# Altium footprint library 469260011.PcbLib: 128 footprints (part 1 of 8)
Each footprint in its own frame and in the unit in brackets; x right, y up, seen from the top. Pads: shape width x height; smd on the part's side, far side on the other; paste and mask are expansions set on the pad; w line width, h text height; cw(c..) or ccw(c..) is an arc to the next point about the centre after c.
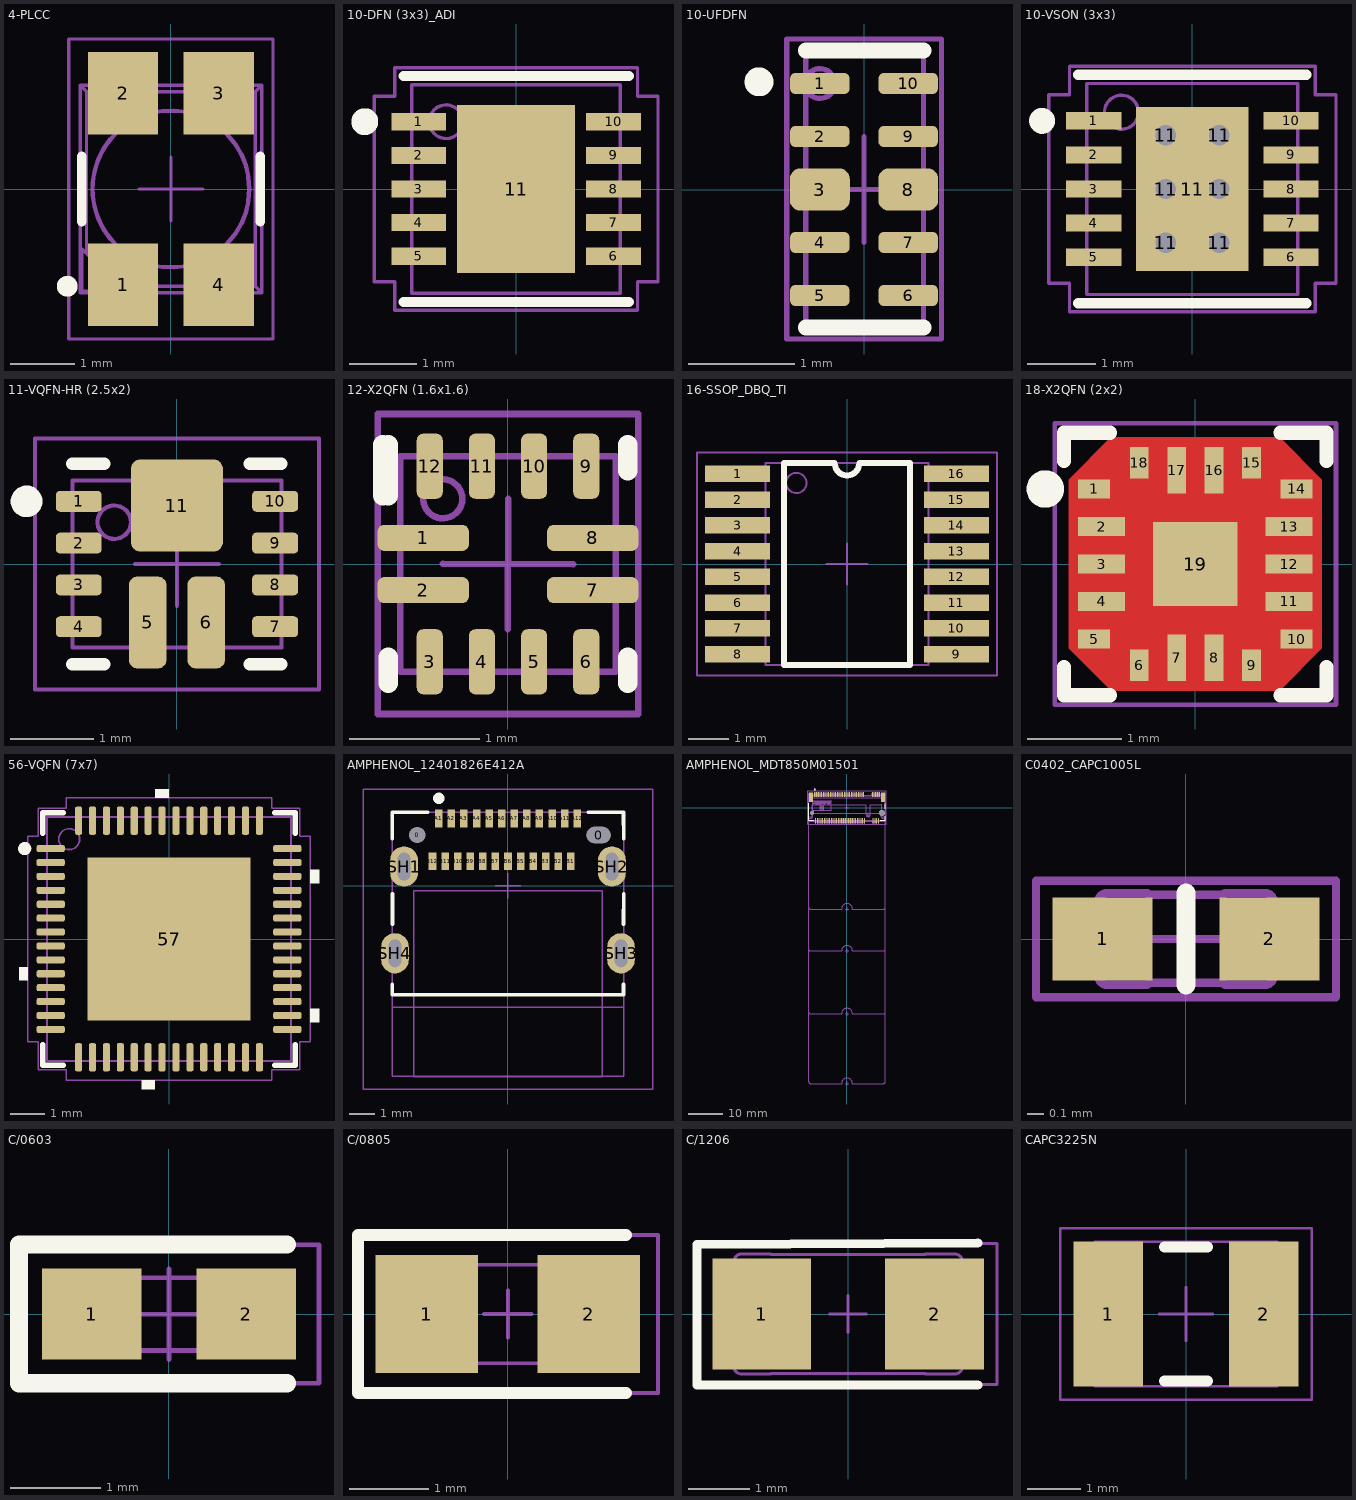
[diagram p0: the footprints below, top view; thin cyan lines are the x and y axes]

## 4-PLCC [mm] "LED RGB DIFFUSED 4PLCC SMD 3.2 x 2.8 x 1.9 mm"
height 1.9
pads (4):
  rect 1.1x1.3 smd: 1(-0.75,-1.5) 2(-0.75,1.5) 3(0.75,1.5) 4(0.75,-1.5)
Top Overlay:
  circle w0.254: c-1.626,-1.524 r0.036
  lines w0.152: -1.397,-0.508 -1.397,0.508 ; 1.397,-0.508 1.397,0.508
Top Assembly:
  circle w0.05: c0,0 r1.23
  circle w0.05: c0,0 r1.219
  circle w0.05: c0,0 r1.238
  lines w0.05: -1.421,-1.624 -1.396,-1.599 ; -1.421,-1.624 -1.421,1.624 ; -1.421,-1.624 1.421,-1.624 ; -1.421,1.624 -1.321,1.524 ; -1.421,1.624 1.421,1.624 ; -1.396,-1.599 -1.396,-0.938 -1.321,-1.012 ; -1.396,-1.599 -0.734,-1.599 -0.809,-1.524 ; -1.321,-1.012 -1.321,1.524 ; -1.321,-1.012 -0.809,-1.524 ; -1.321,1.524 1.321,1.524 ; -1.219,-1.676 -1.219,-1.778 -0.508,-1.778 -0.508,-1.676 ; -1.219,-1.676 -0.508,-1.676 ; -1.219,-1.676 -1.219,-1.626 -1.422,-1.626 -1.422,1.626 -1.219,1.626 -1.219,1.676 ; -1.219,1.676 -1.219,1.778 -0.508,1.778 -0.508,1.676 ; -1.219,1.676 -0.508,1.676 ; -0.809,-1.524 1.321,-1.524 ; -0.508,-1.676 -0.508,-1.626 0.508,-1.626 0.508,-1.676 ; -0.508,1.676 -0.508,1.626 0.508,1.626 0.508,1.676 ; 0.508,-1.676 1.219,-1.676 ; 0.508,-1.676 0.508,-1.778 1.219,-1.778 1.219,-1.676 ; 0.508,1.676 1.219,1.676 ; 0.508,1.676 0.508,1.778 1.219,1.778 1.219,1.676 ; 1.219,-1.676 1.219,-1.626 1.422,-1.626 1.422,1.626 1.219,1.626 1.219,1.676 ; 1.321,-1.524 1.421,-1.624 ; 1.321,-1.524 1.321,1.524 ; 1.321,1.524 1.421,1.624 ; 1.421,-1.624 1.421,1.624
  text ".Designator" at -2.251,-0.226 h1
Top Courtyard:
  lines w0.05: -0.498,0 0.502,0 ; 0,-0.5 0,0.5 ; -1.6,-2.35 -1.6,2.35 1.6,2.35 1.6,-2.35 -1.6,-2.35
3D body "User Library-ASMB-MTB0-0A3A2.step": height 1.9, standoff 0, extent -1.388,-1.75 1.412,1.75

## 10-DFN (3x3)_ADI [mil] "10-Lead Plastic DFN (3mm ? 3mm), 10-WFDFN Exposed Pad"
height 31.5
pads (11):
  rect 32x10 smd paste+0 mask+0: 1(-57,39.37) 2(-57,19.68) 3(-57,0) 4(-57,-19.68) 5(-57,-39.37) 6(57,-39.37) 7(57,-19.68) 8(57,0) 9(57,19.68) 10(57,39.37)
  rect 69x98 smd paste+0 mask+0: 11(0,0)
Top Overlay:
  circle w7.87: c-88.58,39.37 r3.94
  lines w5.91: -66,-66 66,-66 ; -66,66 66,66
Top Assembly:
  circle w1.97: c-41,39.37 r9.84
  lines w1.97: -61,-61 -61,61 61,61 61,-61 -61,-61
  text ".Designator" at -67.02,-8.15 h39.37
Top Courtyard:
  lines w1.97: -19.68,0 19.68,0 ; 0,-19.68 0,19.68 ; -83,-54.37 -71,-54.37 -71,-71 71,-71 71,-54.37 83,-54.37 83,54.37 71,54.37 71,71 -71,71 -71,54.37 -83,54.37 -83,-54.37
3D body "TDFN 10P.STEP": height 30.4, standoff 0.48, extent -59.45,-59.06 59.45,59.05

## 10-UFDFN [mm] "TVS Diode Surface Mount U-DFN2510-10 (2.5x1.0mm)"
height 0.605
pads (10):
  rrect50% 0.56x0.2 smd mask+0.07: 1(-0.417,1) 2(-0.417,0.5) 4(-0.417,-0.5) 5(-0.417,-1) 6(0.417,-1) 7(0.417,-0.5) 9(0.417,0.5) 10(0.417,1)
  rrect50% 0.565x0.4 smd paste-0.02 mask+0.07: 3(-0.417,0) 8(0.417,0)
Top Overlay:
  circle w0.15: c-0.991,1.016 r0.061
  lines w0.15: -0.55,-1.3 0.56,-1.3 ; -0.55,1.31 0.56,1.31
Top Assembly:
  circle w0.05: c-0.417,1 r0.14
  lines w0.05: -0.55,-1.3 0.56,-1.3 0.56,1.3 -0.55,1.3 -0.55,-1.3
  text ".Designator" at -2.252,-0.226 h1
Top Courtyard:
  lines w0.05: -0.5,0 0.5,0 ; 0,-0.5 0,0.5 ; -0.73,-1.41 0.73,-1.41 0.73,1.42 -0.73,1.42 -0.73,-1.41
3D body "PESD1LVDS,115.STEP": height 0.5, standoff 0, extent -0.5,-1.25 0.5,1.25

## 10-VSON (3x3) [mil] "10-VFDFN Exposed Pad, DRC (TI)"
height 39.37
pads (17):
  rect 32x10 smd paste+0 mask+0: 1(-57,39.37) 2(-57,19.68) 3(-57,0) 4(-57,-19.68) 5(-57,-39.37) 6(57,-39.37) 7(57,-19.68) 8(57,0) 9(57,19.68) 10(57,39.37)
  round 31.5 hole 11.81 paste+0 mask-20: 11(-15.5,-31) 11(-15.5,0) 11(-15.5,31) 11(15.5,-31) 11(15.5,0) 11(15.5,31)
  rect 65x95 smd paste-47 mask-47: 11(0,0)
Top Overlay:
  circle w7.87: c-86.84,39.37 r3.54
  lines w5.91: -66,-66 66,-66 ; -66,66 66,66
Top Paste:
  region: 6,-34.94 -6,-34.94 -11.56,-40.5 -11.56,-44.55 11.56,-44.55 11.56,-40.5
  region: -25,-34.94 -29.55,-34.94 -29.55,-44.55 -19.44,-44.55 -19.44,-40.5
  region: 29.55,-34.94 25,-34.94 19.44,-40.5 19.44,-44.55 29.55,-44.55
  region: -25,-3.94 -29.55,-3.94 -29.55,-27.06 -25,-27.06 -19.44,-21.5 -19.44,-9.5
  region: 29.55,-3.94 25,-3.94 19.44,-9.5 19.44,-21.5 25,-27.06 29.55,-27.06
  region: 6,-3.94 -6,-3.94 -11.56,-9.5 -11.56,-21.5 -6,-27.06 6,-27.06 11.56,-21.5 11.56,-9.5
  region: 6,27.06 -6,27.06 -11.56,21.5 -11.56,9.5 -6,3.94 6,3.94 11.56,9.5 11.56,21.5
  region: -25,27.06 -29.55,27.06 -29.55,3.94 -25,3.94 -19.44,9.5 -19.44,21.5
  region: 29.55,27.06 25,27.06 19.44,21.5 19.44,9.5 25,3.94 29.55,3.94
  region: 11.56,44.55 -11.56,44.55 -11.56,40.5 -6,34.94 6,34.94 11.56,40.5
  region: -19.44,44.55 -29.55,44.55 -29.55,34.94 -25,34.94 -19.44,40.5
  region: 29.55,44.55 19.44,44.55 19.44,40.5 25,34.94 29.55,34.94
Top Solder:
  region: -35,-50 -35,-38.87 35,-38.87 35,-50
  region: -35,-23.13 -35,-7.87 35,-7.87 35,-23.13
  region: -35,7.87 -35,23.13 35,23.13 35,7.87
  region: 23.37,-50 23.37,50 35,50 35,-50
  region: 7.63,-50 7.63,50 -7.63,50 -7.63,-50
  region: -35,-50 -35,50 -23.37,50 -23.37,-50
  region: -35,38.87 -35,50 35,50 35,38.87
Top Assembly:
  circle w1.97: c-41,44.37 r9.84
  lines w1.97: -61,-61 61,-61 61,61 -61,61 -61,-61
  text ".Designator" at -88.67,-8.9 h39.37
Top Courtyard:
  lines w1.97: -19.68,0 19.68,0 ; 0,-19.68 0,19.68 ; -83,-54.37 -71,-54.37 -71,-71 71,-71 71,-54.37 83,-54.37 83,54.37 71,54.37 71,71 -71,71 -71,54.37 -83,54.37 -83,-54.37
3D body "SN65HVD01DRCR.step": height 39.37, standoff 0, extent -59.06,-59.06 59.06,59.06

## 11-VQFN-HR (2.5x2) [mm] "2.0-mm x 2.5-mm VQFN HotRod Package (TI)"
height 1
pads (11):
  rrect40% 0.55x0.25 smd mask+0: 1(-1.175,0.75) 2(-1.175,0.25) 3(-1.175,-0.25) 4(-1.175,-0.75) 7(1.175,-0.75) 8(1.175,-0.25) 9(1.175,0.25) 10(1.175,0.75)
  rrect45% 0.45x1.1 smd paste-2 mask+0: 5(-0.35,-0.7) 6(0.35,-0.7)
  rrect19% 1.1x1.1 smd paste-2 mask+0: 11(0,0.7)
Top Overlay:
  circle w0.2: c-1.8,0.75 r0.09
  lines w0.15: -1.25,-1.2 -0.87,-1.2 ; -1.25,1.2 -0.87,1.2 ; 0.87,-1.2 1.25,-1.2 ; 0.87,1.2 1.25,1.2
Top Paste:
  drawing of 5 lines, arcs and shapes, not listed
Top Solder:
  drawing of 11 lines, arcs and shapes, not listed
Top Assembly:
  circle w0.05: c-0.75,0.5 r0.2
  lines w0.05: -1.25,-1 1.25,-1 1.25,1 -1.25,1 -1.25,-1
  text ".Designator" at -2.252,-0.226 h1
Top Courtyard:
  lines w0.05: -0.5,0 0.5,0 ; 0,-0.5 0,0.5 ; -1.7,-1.5 1.7,-1.5 1.7,1.5 -1.7,1.5 -1.7,-1.5
3D body "step_temp.STEP": height 1, standoff 0, extent -1.25,-1 1.25,1

## 12-X2QFN (1.6x1.6) [mm] "12-XFQFN 1.60 mm × 1.60 mm, RWB0012A (TI)"
height 0.4
pads (12):
  rrect50% 0.7x0.2 smd paste-0.337 mask+0.051: 1(-0.65,0.2) 2(-0.65,-0.2) 7(0.65,-0.2) 8(0.65,0.2)
  rrect50% 0.2x0.5 smd paste+0 mask+0.051: 3(-0.6,-0.75) 4(-0.2,-0.75) 5(0.2,-0.75) 6(0.6,-0.75) 9(0.6,0.75) 10(0.2,0.75) 11(-0.2,0.75) 12(-0.6,0.75)
Top Overlay:
  lines w0.15: -0.96,0.525 -0.96,0.914 ; -0.916,-0.914 -0.916,-0.714 ; -0.916,0.525 -0.916,0.914 ; 0.916,-0.914 0.916,-0.714 ; 0.916,0.714 0.916,0.914
Top Assembly:
  circle w0.05: c-0.5,0.5 r0.15
  lines w0.05: -0.825,-0.825 0.825,-0.825 0.825,0.825 -0.825,0.825 -0.825,-0.825
  text "Designator9" at -2.357,-0.227 h1
Top Courtyard:
  lines w0.05: -0.5,0 0.5,0 ; 0,-0.5 0,0.5 ; -1,-1.15 -1,1.15 1,1.15 1,-1.15 -1,-1.15
3D body "TUSB321AIRWBR.step": height 0.4, standoff 0, extent -0.8,-0.8 0.8,0.8

## 16-SSOP_DBQ_TI [mm] "16-SSOP (0.154\", 3.90mm Width), MO-137"
height 1.75
pads (16):
  rect 1.6x0.41 smd: 1(-2.7,2.223) 2(-2.7,1.588) 3(-2.7,0.953) 4(-2.7,0.318) 5(-2.7,-0.318) 6(-2.7,-0.953) 7(-2.7,-1.588) 8(-2.7,-2.223) 9(2.7,-2.223) 10(2.7,-1.588) 11(2.7,-0.953) 12(2.7,-0.318) 13(2.7,0.318) 14(2.7,0.953) 15(2.7,1.588) 16(2.7,2.223)
Top Overlay:
  lines w0.15: -1.549,-2.489 -1.549,2.489 -0.305,2.489 ccw(c0,2.489) 0.305,2.489 1.549,2.489 1.549,-2.489 -1.549,-2.489
Top Assembly:
  circle w0.05: c-1.25,2 r0.25
  lines w0.05: -0.305,2.489 ccw(c0,2.489) 0.305,2.489 ; -0.305,2.489 -2.007,2.489 -2.007,-2.489 2.007,-2.489 2.007,2.489 0.305,2.489 ; -0.305,2.489 0.305,2.489 ; 3.099,-2.362 3.099,-2.083 ; 3.099,-2.362 2.007,-2.362 2.007,-2.083 3.099,-2.083 ; 3.099,-2.362 3.099,-2.083 ; 3.099,-1.727 3.099,-1.448 ; 3.099,-1.727 3.099,-1.448 ; 3.099,-1.727 2.007,-1.727 2.007,-1.448 3.099,-1.448 ; 3.099,-1.092 3.099,-0.813 ; 3.099,-1.092 3.099,-0.813 ; 3.099,-1.092 2.007,-1.092 2.007,-0.813 3.099,-0.813 ; 3.099,-0.457 3.099,-0.178 ; 3.099,-0.457 2.007,-0.457 2.007,-0.178 3.099,-0.178 ; 3.099,-0.457 3.099,-0.178 ; 3.099,0.178 3.099,0.457 ; 3.099,0.178 2.007,0.178 2.007,0.457 3.099,0.457 ; 3.099,0.178 3.099,0.457 ; 3.099,0.813 3.099,1.092 ; 3.099,0.813 3.099,1.092 ; 3.099,0.813 2.007,0.813 2.007,1.092 3.099,1.092 ; 3.099,1.448 2.007,1.448 2.007,1.727 3.099,1.727 ; 3.099,1.448 3.099,1.727 ; 3.099,1.448 3.099,1.727 ; 3.099,2.083 3.099,2.362 ; 3.099,2.083 3.099,2.362 ; 3.099,2.083 2.007,2.083 2.007,2.362 3.099,2.362 ; -3.099,-2.362 -2.007,-2.362 -2.007,-2.083 -3.099,-2.083 -3.099,-2.362 ; -3.099,-1.727 -2.007,-1.727 -2.007,-1.448 -3.099,-1.448 -3.099,-1.727 ; -3.099,-1.092 -2.007,-1.092 -2.007,-0.813 -3.099,-0.813 -3.099,-1.092 ; -3.099,-0.457 -2.007,-0.457 -2.007,-0.178 -3.099,-0.178 -3.099,-0.457 ; -3.099,0.178 -2.007,0.178 -2.007,0.457 -3.099,0.457 -3.099,0.178 ; -3.099,0.813 -3.099,1.092 -2.007,1.092 -2.007,0.813 -3.099,0.813 ; -3.099,1.448 -2.007,1.448 -2.007,1.727 -3.099,1.727 -3.099,1.448 ; -3.099,2.083 -2.007,2.083 -2.007,2.362 -3.099,2.362 -3.099,2.083
  text ".Designator" at -2.252,-0.226 h1
Top Courtyard:
  lines w0.05: -0.5,0 0.5,0 ; 0,-0.5 0,0.5 ; -3.7,-2.75 3.7,-2.75 3.7,-2.413 3.7,2.75 -3.7,2.75 -3.7,-2.75
3D body "AMC6821SDBQR.step": height 1.75, standoff 0, extent -2.997,-2.451 2.997,2.451

## 18-X2QFN (2x2) [mm] "18-XFQFN Exposed Pad (DIO)"
height 1
pads (19):
  rect 0.34x0.2 smd: 1(-1.08,0.8) 5(-1.08,-0.8) 10(1.08,-0.8) 14(1.08,0.8)
  rect 0.5x0.2 smd: 2(-1,0.4) 3(-1,0) 4(-1,-0.4) 11(1,-0.4) 12(1,0) 13(1,0.4)
  rect 0.2x0.34 smd: 6(-0.6,-1.08) 9(0.6,-1.08) 15(0.6,1.08) 18(-0.6,1.08)
  rect 0.2x0.5 smd: 7(-0.2,-1) 8(0.2,-1) 16(0.2,1) 17(-0.2,1)
  rect 0.9x0.9 smd paste-0.148: 19(0,0)
Top Layer:
  region: -0.5,-1.25 -0.7,-1.25 -0.7,-0.91 -0.54,-0.75 -0.5,-0.75
  region: -0.75,-0.74 -0.91,-0.9 -1.25,-0.9 -1.25,-0.7 -0.91,-0.7 -0.75,-0.7
  region: 0.54,0.75 0.5,0.75 0.5,1.25 0.7,1.25 0.7,0.91
  region: 1.25,0.9 1.25,0.7 0.75,0.7 0.75,0.74 0.91,0.9
  region: 0.7,-0.91 0.7,-1.25 0.5,-1.25 0.5,-0.91 0.5,-0.75 0.54,-0.75
  region: 1.25,-0.9 0.91,-0.9 0.75,-0.74 0.75,-0.7 1.25,-0.7
  region: -0.5,0.75 -0.54,0.75 -0.7,0.91 -0.7,1.25 -0.5,1.25
  region: -0.75,0.74 -0.75,0.7 -1.25,0.7 -1.25,0.9 -0.91,0.9
  pour cut-out: -0.9,1.35 0.9,1.35 1.35,0.9 1.35,-0.9 0.9,-1.35 -0.9,-1.35 -1.35,-0.9 -1.35,0.9
Top Overlay:
  circle w0.2: c-1.6,0.8 r0.1
  lines w0.15: -1.4,-1.1 -1.4,-1.4 -0.91,-1.4 ; -1.4,1.1 -1.4,1.4 -0.91,1.4 ; 0.91,-1.4 1.4,-1.4 1.4,-1.1 ; 0.91,1.4 1.4,1.4 1.4,1.1
Top Paste:
  region: -0.5,-0.91 -0.7,-0.91 -0.54,-0.75 -0.5,-0.75
  region: -0.75,-0.74 -0.91,-0.9 -0.91,-0.7 -0.75,-0.7
  region: 0.54,0.75 0.5,0.75 0.5,0.91 0.7,0.91
  region: 0.91,0.7 0.75,0.7 0.75,0.74 0.91,0.9
  region: 0.7,-0.91 0.5,-0.91 0.5,-0.75 0.54,-0.75
  region: 0.91,-0.9 0.75,-0.74 0.75,-0.7 0.91,-0.7
  region: -0.5,0.75 -0.54,0.75 -0.7,0.91 -0.5,0.91
  region: -0.75,0.74 -0.75,0.7 -0.91,0.7 -0.91,0.9
Top Solder:
  region: -0.7,0.8 -0.65,0.75 -0.65,0.6 -1.35,0.6 -1.35,1 -0.9,1
  region: -0.4,0.65 -0.55,0.65 -0.8,0.9 -0.8,1.35 -0.4,1.35
  region: 0.8,0.9 0.55,0.65 0.4,0.65 0.4,1.35 0.8,1.35
  region: 1.35,0.6 0.65,0.6 0.65,0.75 0.9,1 1.35,1
  region: -0.65,-0.75 -0.9,-1 -1.35,-1 -1.35,-0.6 -0.65,-0.6
  region: -0.4,-1.35 -0.8,-1.35 -0.8,-0.9 -0.55,-0.65 -0.4,-0.65
  region: 0.8,-0.9 0.8,-1.35 0.4,-1.35 0.4,-0.65 0.55,-0.65
  region: 1.35,-1 0.9,-1 0.65,-0.75 0.65,-0.6 1.35,-0.6
Top Assembly:
  circle w0.05: c-0.55,0.6 r0.2
  lines w0.05: -1,-1 1,-1 1,1 -1,1 -1,-1
  text ".Designator" at -2.433,-0.226 h1
Top Courtyard:
  lines w0.05: -0.5,0 0.5,0 ; 0,-0.5 0,0.5 ; -1.5,-1.5 1.5,-1.5 1.5,1.5 -1.5,1.5 -1.5,-1.5
3D body "step_temp.STEP": height 0.4, standoff 0, extent -1,-1 1,1

## 56-VQFN (7x7) [mm] "56-VFQFN Exposed Pad, 0.4 mm pitch"
height 14
pads (57):
  rrect50% 0.808x0.204 smd paste+0 mask+0: 1(-3.401,2.6) 2(-3.401,2.2) 3(-3.401,1.8) 4(-3.401,1.4) 5(-3.401,1) 6(-3.401,0.6) 7(-3.401,0.2) 8(-3.401,-0.2) 9(-3.401,-0.6) 10(-3.401,-1) 11(-3.401,-1.4) 12(-3.401,-1.8) 13(-3.401,-2.2) 14(-3.401,-2.6) 29(3.401,-2.6) 30(3.401,-2.2) 31(3.401,-1.8) 32(3.401,-1.4) 33(3.401,-1) 34(3.401,-0.6) 35(3.401,-0.2) 36(3.401,0.2) 37(3.401,0.6) 38(3.401,1) 39(3.401,1.4) 40(3.401,1.8) 41(3.401,2.2) 42(3.401,2.6)
  rrect50% 0.204x0.808 smd paste+0 mask+0: 15(-2.6,-3.401) 16(-2.2,-3.401) 17(-1.8,-3.401) 18(-1.4,-3.401) 19(-1,-3.401) 20(-0.6,-3.401) 21(-0.2,-3.401) 22(0.2,-3.401) 23(0.6,-3.401) 24(1,-3.401) 25(1.4,-3.401) 26(1.8,-3.401) 27(2.2,-3.401) 28(2.6,-3.401) 43(2.6,3.401) 44(2.2,3.401) 45(1.8,3.401) 46(1.4,3.401) 47(1,3.401) 48(0.6,3.401) 49(0.2,3.401) 50(-0.2,3.401) 51(-0.6,3.401) 52(-1,3.401) 53(-1.4,3.401) 54(-1.8,3.401) 55(-2.2,3.401) 56(-2.6,3.401)
  rect 4.699x4.699 smd paste-2.349 mask+0: 57(0,0)
Top Overlay:
  circle w0.2: c-4.15,2.6 r0.09
  region: -0.009,4.059 -0.39,4.059 -0.39,4.313 -0.009,4.313
  region: 4.059,1.99 4.313,1.99 4.313,1.609 4.059,1.609
  region: 4.059,-2.01 4.313,-2.01 4.313,-2.391 4.059,-2.391
  region: -0.409,-4.059 -0.79,-4.059 -0.79,-4.313 -0.409,-4.313
  region: -4.059,-0.81 -4.313,-0.81 -4.313,-1.191 -4.059,-1.191
  lines w0.152: -3.632,-3.035 -3.632,-3.632 -3.035,-3.632 ; -3.632,3.035 -3.632,3.632 -3.035,3.632 ; 3.035,-3.632 3.632,-3.632 3.632,-3.035 ; 3.035,3.632 3.632,3.632 3.632,3.035
Top Paste:
  region: 2.25,-0.883 0.883,-0.883 0.883,-2.25 2.25,-2.25
  region: 2.25,0.683 0.883,0.683 0.883,-0.683 2.25,-0.683
  region: 2.25,2.25 0.883,2.25 0.883,0.883 2.25,0.883
  region: 0.683,-0.883 -0.683,-0.883 -0.683,-2.25 0.683,-2.25
  region: 0.683,0.683 -0.683,0.683 -0.683,-0.683 0.683,-0.683
  region: 0.683,2.25 -0.683,2.25 -0.683,0.883 0.683,0.883
  region: -0.883,-0.883 -2.25,-0.883 -2.25,-2.25 -0.883,-2.25
  region: -0.883,0.683 -2.25,0.683 -2.25,-0.683 -0.883,-0.683
  region: -0.883,2.25 -2.25,2.25 -2.25,0.883 -0.883,0.883
Top Assembly:
  circle w0.05: c-2.87,2.87 r0.3
  lines w0.05: -3.505,-3.505 -3.505,3.505 3.505,3.505 3.505,-3.505 -3.505,-3.505 ; -3.505,-2.727 -3.505,-2.473 -3.505,-2.727 ; -3.505,-2.327 -3.505,-2.073 -3.505,-2.327 ; -3.505,-1.927 -3.505,-1.673 -3.505,-1.927 ; -3.505,-1.527 -3.505,-1.273 -3.505,-1.527 ; -3.505,-1.127 -3.505,-0.873 -3.505,-1.127 ; -3.505,-0.727 -3.505,-0.473 -3.505,-0.727 ; -3.505,-0.327 -3.505,-0.073 -3.505,-0.327 ; -3.505,0.073 -3.505,0.327 -3.505,0.073 ; -3.505,0.473 -3.505,0.727 -3.505,0.473 ; -3.505,0.873 -3.505,1.127 -3.505,0.873 ; -3.505,1.273 -3.505,1.527 -3.505,1.273 ; -3.505,1.673 -3.505,1.927 -3.505,1.673 ; -3.505,2.073 -3.505,2.327 -3.505,2.073 ; -3.505,2.473 -3.505,2.727 -3.505,2.473 ; -2.727,-3.505 -2.473,-3.505 -2.727,-3.505 ; -2.727,3.505 -2.473,3.505 -2.727,3.505 ; -2.327,-3.505 -2.073,-3.505 -2.327,-3.505 ; -2.327,3.505 -2.073,3.505 -2.327,3.505 ; -1.927,-3.505 -1.673,-3.505 -1.927,-3.505 ; -1.927,3.505 -1.673,3.505 -1.927,3.505 ; -1.527,-3.505 -1.273,-3.505 -1.527,-3.505 ; -1.527,3.505 -1.273,3.505 -1.527,3.505 ; -1.127,-3.505 -0.873,-3.505 -1.127,-3.505 ; -1.127,3.505 -0.873,3.505 -1.127,3.505 ; -0.727,-3.505 -0.473,-3.505 -0.727,-3.505 ; -0.727,3.505 -0.473,3.505 -0.727,3.505 ; -0.327,-3.505 -0.073,-3.505 -0.327,-3.505 ; -0.327,3.505 -0.073,3.505 -0.327,3.505 ; 0.073,-3.505 0.327,-3.505 0.073,-3.505 ; 0.073,3.505 0.327,3.505 0.073,3.505 ; 0.473,-3.505 0.727,-3.505 0.473,-3.505 ; 0.473,3.505 0.727,3.505 0.473,3.505 ; 0.873,-3.505 1.127,-3.505 0.873,-3.505 ; 0.873,3.505 1.127,3.505 0.873,3.505 ; 1.273,-3.505 1.527,-3.505 1.273,-3.505 ; 1.273,3.505 1.527,3.505 1.273,3.505 ; 1.673,-3.505 1.927,-3.505 1.673,-3.505 ; 1.673,3.505 1.927,3.505 1.673,3.505 ; 2.073,-3.505 2.327,-3.505 2.073,-3.505 ; 2.073,3.505 2.327,3.505 2.073,3.505 ; 2.473,-3.505 2.727,-3.505 2.473,-3.505 ; 2.473,3.505 2.727,3.505 2.473,3.505 ; 3.505,-2.727 3.505,-2.473 3.505,-2.727 ; 3.505,-2.327 3.505,-2.073 3.505,-2.327 ; 3.505,-1.927 3.505,-1.673 3.505,-1.927 ; 3.505,-1.527 3.505,-1.273 3.505,-1.527 ; 3.505,-1.127 3.505,-0.873 3.505,-1.127 ; 3.505,-0.727 3.505,-0.473 3.505,-0.727 ; 3.505,-0.327 3.505,-0.073 3.505,-0.327 ; 3.505,0.073 3.505,0.327 3.505,0.073 ; 3.505,0.473 3.505,0.727 3.505,0.473 ; 3.505,0.873 3.505,1.127 3.505,0.873 ; 3.505,1.273 3.505,1.527 3.505,1.273 ; 3.505,1.673 3.505,1.927 3.505,1.673 ; 3.505,2.073 3.505,2.327 3.505,2.073 ; 3.505,2.473 3.505,2.727 3.505,2.473
  text ".Designator" at -2.434,-0.226 h1
Top Courtyard:
  lines w0.05: -0.5,0 0.5,0 ; 0,-0.5 0,0.5 ; -4.059,-2.956 -4.059,2.956 -3.759,2.956 -3.759,3.759 -2.956,3.759 -2.956,4.059 2.956,4.059 2.956,3.759 3.759,3.759 3.759,2.956 4.059,2.956 4.059,-2.956 3.759,-2.956 3.759,-3.759 2.956,-3.759 2.956,-4.059 -2.956,-4.059 -2.956,-3.759 -3.759,-3.759 -3.759,-2.956 -4.059,-2.956
3D body "VQFN56_2G_MCH.step": height 0.99, standoff 0, extent -3.505,-3.505 3.505,3.505

## AMPHENOL_12401826E412A [mm]
height 3.28
pads (30):
  round 0.325 hole 0.65 unplated: 0(-3.6,2.02)
  oval 0.95x0.65 hole 0.65 slot 0.95 at 0 deg unplated: 0(3.6,2.02)
  rect 0.3x0.7 smd: A1(-2.75,2.68) A2(-2.25,2.68) A3(-1.75,2.68) A4(-1.25,2.68) A5(-0.75,2.68) A6(-0.25,2.68) A7(0.25,2.68) A8(0.75,2.68) A9(1.25,2.68) A10(1.75,2.68) A11(2.25,2.68) A12(2.75,2.68) B1(2.5,0.98) B2(2,0.98) B3(1.5,0.98) B4(1,0.98) B5(0.5,0.98) B6(0,0.98) B7(-0.5,0.98) B8(-1,0.98) B9(-1.5,0.98) B10(-2,0.98) B11(-2.5,0.98) B12(-3,0.98)
  oval 1.1x1.6 hole 0.5 slot 1.1 at 90 deg: SH1(-4.13,0.77) SH2(4.13,0.77) SH3(4.49,-2.68) SH4(-4.49,-2.68)
Top Overlay:
  circle w0.25: c-2.75,3.48 r0.1
  lines w0.15: -4.6,-3.92 -4.6,-4.326 4.59,-4.326 4.59,-3.92 ; -4.6,1.88 -4.6,2.93 -3.2,2.93 ; -4.59,-1.52 -4.59,-0.32 ; 3.2,2.93 4.59,2.93 4.6,1.88 ; 4.59,-1.52 4.6,-0.32
Mechanical 1:
  lines w0.05: -3.75,-7.578 -3.75,-0.186 3.75,-0.186 3.75,-7.578 -3.75,-7.578
  text "Keep out / zone" at -2.769,-3.615 h0.76
Top Assembly:
  lines w0.05: -4.59,-4.826 4.59,-4.826 ; -4.59,-7.57 4.59,-7.57 4.59,2.93 -4.59,2.93 -4.59,-7.57
  text ".Designator" at -2.252,-0.226 h1
Top Courtyard:
  lines w0.05: -0.5,0 0.5,0 ; 0,-0.5 0,0.5 ; -5.75,-8.07 -5.75,3.85 5.75,3.85 5.75,-8.07 -5.75,-8.07
3D body "C12401826_2.stp": height 3.2, standoff -1.98, extent -4.605,-7.565 4.595,2.935

## AMPHENOL_MDT850M01501 [mm] "CONN M.2 FMALE 75POS 0.020 GOLD H=8.5mm"
height 8.5
pads (71):
  rect 0.3x1.55 smd mask+0.05: 1(-9.25,3.775) 2(-9,-3.775) 3(-8.75,3.775) 4(-8.5,-3.775) 5(-8.25,3.775) 6(-8,-3.775) 7(-7.75,3.775) 8(-7.5,-3.775) 9(-7.25,3.775) 10(-7,-3.775) 11(-6.75,3.775) 12(-6.5,-3.775) 13(-6.25,3.775) 14(-6,-3.775) 15(-5.75,3.775) 16(-5.5,-3.775) 17(-5.25,3.775) 18(-5,-3.775) 19(-4.75,3.775) 20(-4.5,-3.775) 21(-4.25,3.775) 22(-4,-3.775) 23(-3.75,3.775) 24(-3.5,-3.775) 25(-3.25,3.775) 26(-3,-3.775) 27(-2.75,3.775) 28(-2.5,-3.775) 29(-2.25,3.775) 30(-2,-3.775) 31(-1.75,3.775) 32(-1.5,-3.775) 33(-1.25,3.775) 34(-1,-3.775) 35(-0.75,3.775) 36(-0.5,-3.775) 37(-0.25,3.775) 38(0,-3.775) 39(0.25,3.775) 40(0.5,-3.775) 41(0.75,3.775) 42(1,-3.775) 43(1.25,3.775) 44(1.5,-3.775) 45(1.75,3.775) 46(2,-3.775) 47(2.25,3.775) 48(2.5,-3.775) 49(2.75,3.775) 50(3,-3.775) 51(3.25,3.775) 52(3.5,-3.775) 53(3.75,3.775) 54(4,-3.775) 55(4.25,3.775) 56(4.5,-3.775) 57(4.75,3.775) 58(5,-3.775) 67(7.25,3.775) 68(7.5,-3.775) 69(7.75,3.775) 70(8,-3.775) 71(8.25,3.775) 72(8.5,-3.775) 73(8.75,3.775) 74(9,-3.775) 75(9.25,3.775)
  rect 1.2x2.75 smd: SH1(-10.35,3) SH2(10.35,3)
  round 1.15 hole 1.15 unplated: ""(-10,-1.5)
  round 1.65 hole 1.65 unplated: ""(10,-1.5)
Top Overlay:
  circle w0.2: c-9.25,5.25 r0.1
  lines w0.127: -10.95,1.305 -10.95,-3.67 -9.47,-3.67 ; 9.47,-3.67 10.95,-3.67 10.95,-2.5 ; 10.95,-0.25 10.95,1.1
Mechanical 1:
  lines w0.05: -11,-58.6 ccw(c-10.5,-58.6) -10.5,-59.1 -1.575,-59.1 cw(c0,-59.1) 1.575,-59.1 10.5,-59.1 ccw(c10.5,-58.6) 11,-58.6 ; -11,-28.6 ccw(c-10.5,-28.6) -10.5,-29.1 -1.575,-29.1 cw(c0,-29.1) 1.575,-29.1 10.5,-29.1 ccw(c10.5,-28.6) 11,-28.6 ; -0.5,-79.1 0.5,-79.1 ; -0.5,-59.1 0.5,-59.1 ; -0.5,-41.1 0.5,-41.1 ; -0.5,-29.1 0.5,-29.1 ; 0,-79.6 0,-78.6 ; 0,-59.6 0,-58.6 ; 0,-41.6 0,-40.6 ; 0,-29.6 0,-28.6 ; 5.625,-2 6.625,-2 ; 6.125,-2.5 6.125,-1.5 ; -11,-40.6 ccw(c-10.5,-40.6) -10.5,-41.1 -1.575,-41.1 cw(c0,-41.1) 1.575,-41.1 10.5,-41.1 ccw(c10.5,-40.6) 11,-40.6 ; -11,-40.6 -11,-78.6 ccw(c-10.5,-78.6) -10.5,-79.1 -1.575,-79.1 cw(c0,-79.1) 1.575,-79.1 10.5,-79.1 ccw(c10.5,-78.6) 11,-78.6 11,-40.6 ; -11,-40.6 -11,-3.3 cw(c-10.8,-3.3) -10.8,-3.1 -10.45,-3.1 ccw(c-10.45,-2.6) -9.95,-2.6 -9.95,0.7 cw(c-9.75,0.7) -9.75,0.9 5.525,0.9 5.525,-2 ccw(c6.125,-2) 6.125,-2.6 ccw(c6.125,-2) 6.725,-2 6.725,0.9 9.75,0.9 cw(c9.75,0.7) 9.95,0.7 9.95,-2.6 ccw(c10.45,-2.6) 10.45,-3.1 10.8,-3.1 cw(c10.8,-3.3) 11,-3.3 11,-40.6
  text "Type 2260" at 4.293,-58.828 h1
  text "Type 2280" at 4.293,-78.828 h1
  text "Type 2230" at 4.293,-28.828 h1
  text "Type 2242" at 4.296,-40.828 h1
Top 3D Body:
  circle w0.2: c-9.25,5.25 r0.1
  lines w0.127: -10.95,-3.67 10.95,-3.67 10.95,3.53 -10.95,3.53 -10.95,-3.67
Top Assembly:
  drawing of 2440 lines, arcs and shapes, not listed
  text ".Designator" at -2.252,-0.226 h1
  text ".Designator" at -2.252,-0.226 h1
Top Courtyard:
  lines w0.05: -0.5,0 0.5,0 ; 0,-0.5 0,0.5 ; -11.2,-4.8 11.2,-4.8 11.2,4.8 -11.2,4.8 -11.2,-4.8
3D body "User Library-2280-D2-M-B.step": height 8.95, standoff 5.45, extent -11,-79.1 11,0.9
3D body "mdt850m01501_c3d.stp": height 8.5, standoff -0.5, extent -10.95,-4.45 10.95,3.95

## C0402_CAPC1005L [mm] "Chip Capacitor, Body 1.0x0.5mm, IPC High Density"
height 0.6
pads (2):
  rect 0.6x0.5 smd: 1(-0.5,0) 2(0.5,0)
Top Overlay:
  lines w0.115: 0,-0.274 0,0.276
Top Assembly:
  lines w0.05: -0.525,-0.224 ccw(c-0.475,-0.224) -0.475,-0.274 -0.237,-0.274 ccw(c-0.237,-0.262) -0.225,-0.262 0.225,-0.263 ccw(c0.237,-0.262) 0.237,-0.274 0.475,-0.274 ccw(c0.475,-0.224) 0.525,-0.224 0.525,0.226 ccw(c0.475,0.226) 0.475,0.276 0.237,0.276 ccw(c0.237,0.264) 0.225,0.264 -0.225,0.265 ccw(c-0.237,0.264) -0.237,0.276 -0.475,0.276 ccw(c-0.475,0.226) -0.525,0.226 -0.525,-0.224
  text ".Designator" at -2.252,-0.226 h1
Top Courtyard:
  lines w0.05: -0.3,0 0.3,0 ; 0,-0.3 0,0.3 ; -0.9,-0.35 -0.9,0.35 0.9,0.35 0.9,-0.35 -0.9,-0.35
3D body "c0402c153k5ractu.stp": height 0.54, standoff -0.01, extent -0.525,-0.274 0.525,0.276

## C/0603 [mm]
height 14
pads (2):
  rect 1.1x1 smd: 1(-0.85,0) 2(0.85,0)
Top Overlay:
  lines w0.2: 1.3,-0.76 -1.651,-0.76 -1.651,0.766 1.3,0.766
Top Assembly:
  lines w0.05: -0.8,-0.4 -0.8,0.4 0.8,0.4 0.8,-0.4 -0.8,-0.4
  text ".Designator" at -2.252,-0.226 h1
Top Courtyard:
  lines w0.05: -0.5,0 0.5,0 ; 0,-0.5 0,0.5 ; -1.651,-0.762 -1.651,0.762 1.651,0.762 1.651,-0.762 -1.651,-0.762
3D body "User Library-CapCeramic_Kemet_0603_1608.step": height 0.8, standoff 0, extent -0.8,-0.4 0.8,0.4

## C/0805 [mm]
height 14
pads (2):
  rect 1.3x1.5 smd: 1(-1.025,0) 2(1.025,0)
Top Overlay:
  lines w0.15: 1.5,-1 -1.9,-1 -1.9,1 1.5,1
Top Assembly:
  lines w0.05: -0.49,-0.645 -0.95,-0.645 cw(c-0.95,-0.595) -1,-0.595 -1,0.595 cw(c-0.95,0.595) -0.95,0.645 -0.49,0.645 ; -0.49,-0.625 0.49,-0.625 ; -0.49,0.625 0.49,0.625 ; 0.49,-0.645 0.95,-0.645 ccw(c0.95,-0.595) 1,-0.595 1,0.595 ccw(c0.95,0.595) 0.95,0.645 0.49,0.645
  text ".Designator" at -2.252,-0.226 h1
Top Courtyard:
  lines w0.05: -0.3,0 0.3,0 ; 0,-0.3 0,0.3 ; -1.9,-1 -1.9,1 1.905,1 1.905,-1 -1.9,-1
3D body "User Library-User Library-0805(2012M) Cap.step": height 1.3, standoff 0.01, extent -1,-0.645 1,0.645

## C/1206 [mm]
height 1.8
pads (2):
  rect 1.6x1.8 smd: 1(-1.4,0) 2(1.4,0)
Top Overlay:
  lines w0.15: 2.1,-1.15 -2.45,-1.15 -2.45,1.126 2.1,1.15
Top Assembly:
  lines w0.05: -1.85,-0.85 ccw(c-1.725,-0.85) -1.725,-0.975 -1.262,-0.975 ccw(c-1.262,-0.963) -1.25,-0.964 1.25,-0.964 ccw(c1.262,-0.963) 1.262,-0.975 1.725,-0.975 ccw(c1.725,-0.85) 1.85,-0.85 1.85,0.85 ccw(c1.725,0.85) 1.725,0.975 1.262,0.975 ccw(c1.262,0.963) 1.25,0.964 -1.25,0.964 ccw(c-1.262,0.963) -1.262,0.975 -1.725,0.975 ccw(c-1.725,0.85) -1.85,0.85 -1.85,-0.85
  text ".Designator" at -2.252,-0.226 h1
Top Courtyard:
  lines w0.05: -0.3,0 0.3,0 ; 0,-0.3 0,0.3 ; -2.413,-1.143 2.413,-1.143 2.413,1.143 -2.413,1.143 ; -2.413,-1.143 -2.413,1.143 ; -2.413,-1.143 -2.413,1.143
3D body "c1206x223j2gacauto.stp": height 1.84, standoff 0.04, extent -1.85,-0.975 1.85,0.975

## CAPC3225N [mm] "Chip Capacitor, Body 3.2x2.5mm (1210), IPC Medium Density"
height 1.35
pads (2):
  rect 1.3x2.7 smd: 1(-1.45,0) 2(1.45,0)
Top Overlay:
  lines w0.2: -0.4,-1.25 0.4,-1.25 ; -0.4,1.25 0.4,1.25
Top Assembly:
  lines w0.05: -1.7,-1.35 1.7,-1.35 1.7,1.35 -1.7,1.35 -1.7,-1.35
  text ".Designator" at -2.252,-0.226 h1
Top Courtyard:
  lines w0.05: -0.5,0 0.5,0 ; 0,-0.5 0,0.5 ; -2.35,-1.6 -2.35,1.6 2.35,1.6 2.35,-1.6 -2.35,-1.6
3D body "User Library-CAPC3225.step": height 2.5, standoff 0, extent -1.6,-1.25 1.6,1.25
